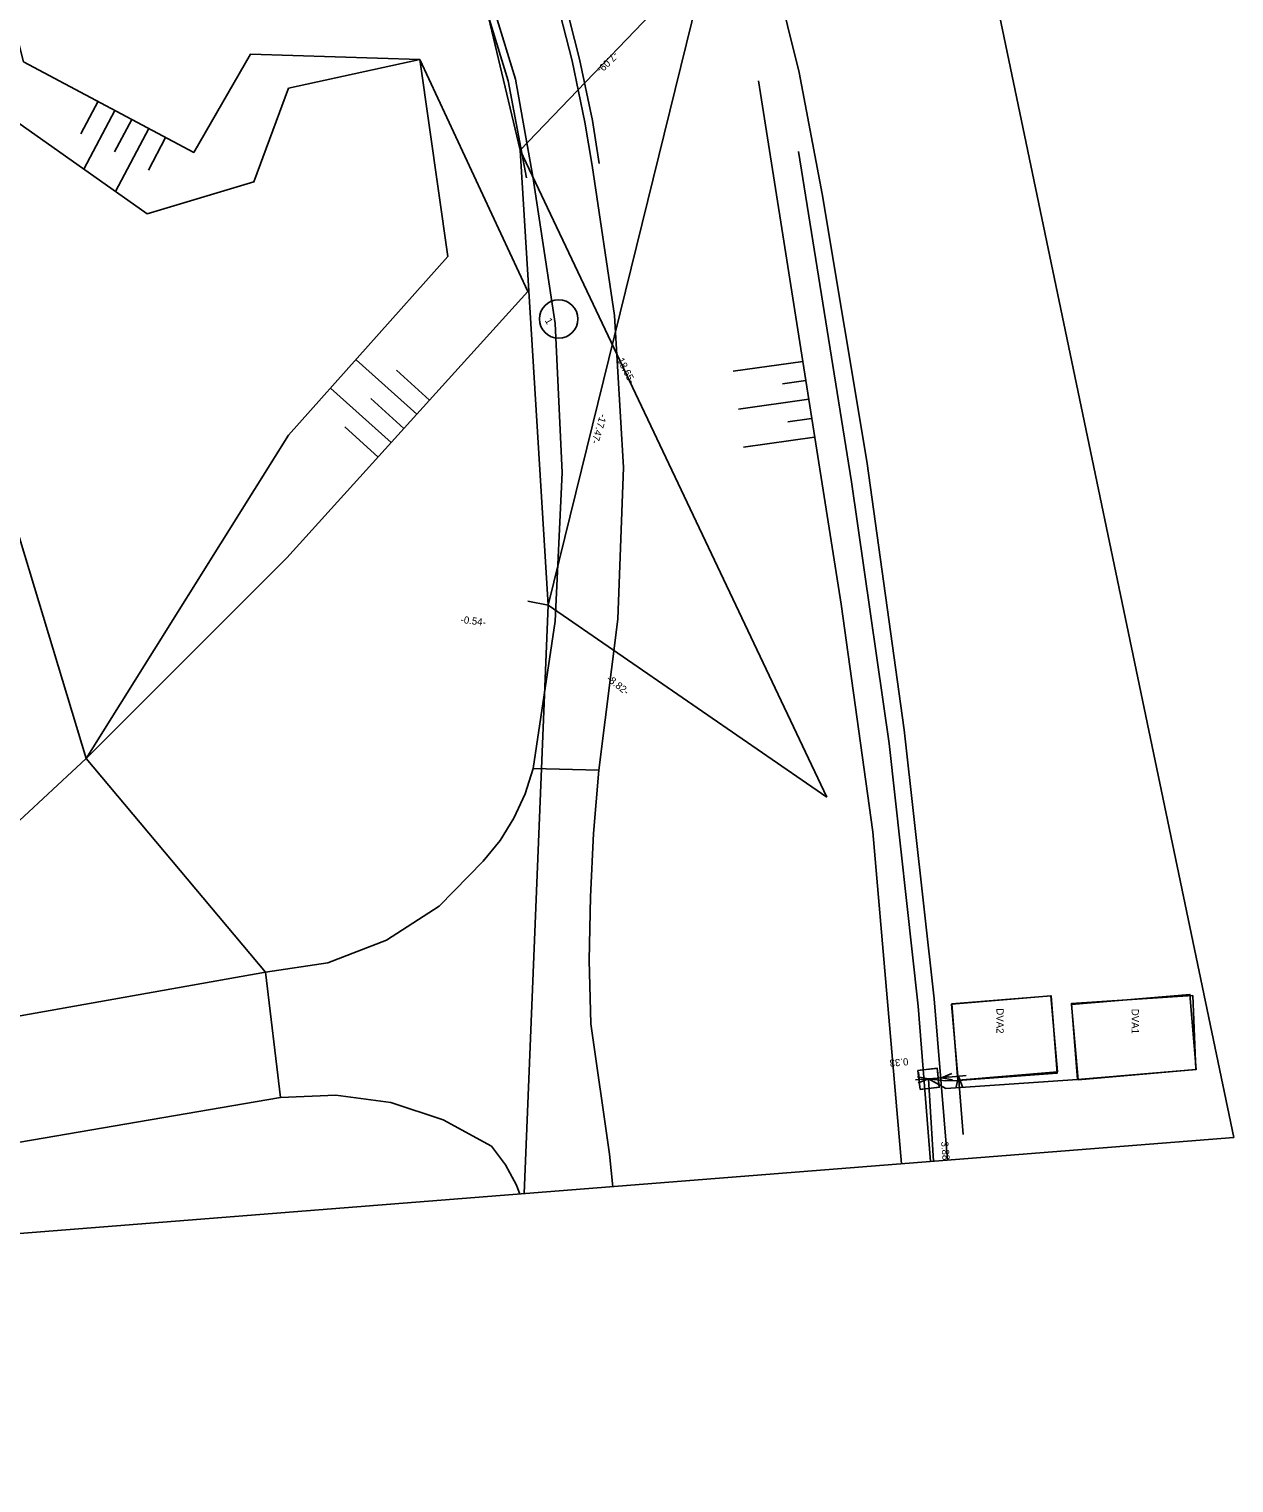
# Model space of a CAD drawing. Extents: x -597791 to -597535, y -1159670 to -1159547.
# Drawn here: x -597686.05 to -597654.67, y -1159669.54 to -1159631.67 of the extents above; entities that cross this region are included whole.
import ezdxf

# ---------------------------------------------------------------- set-up
doc = ezdxf.new("R2010")
doc.units = 0
for name, color, linetype in [('Kabely SSZ silové_Kabel SSZ_ kab', 7, 'Continuous'), ('Kabely SSZ silové_Oměrná SSZ', 7, 'Continuous'), ('Kabely SSZ silové_Text SSZ', 7, 'Continuous'), ('Koordinační kabel-Pom_KK Metalic', 7, 'Continuous'), ('Koordinační kabel-Pom_Oměrná KKM', 7, 'Continuous'), ('Koordinační kabel-Pom_Text KKM', 7, 'Continuous'), ('Koordinační kabel-Pom_Šachty KKM', 7, 'Continuous'), ('MAPA', 7, 'Continuous'), ('Ostatní', 7, 'Continuous'), ('Žádosti', 7, 'Continuous')]:
    doc.layers.add(name, color=color, linetype=linetype)

msp = doc.modelspace()

# ---------------------------------------------------------------- linework, layer by layer
at = {"layer": 'Kabely SSZ silové_Kabel SSZ_ kab'}
msp.add_line((-597662.49, -1159661.158), (-597662.62, -1159659.01), dxfattribs=at)
for points in [[(-597662.62, -1159659.01), (-597662.17, -1159659.26), (-597658.74, -1159659.03), (-597655.66, -1159658.77), (-597655.74, -1159656.84), (-597658.9, -1159657.05), (-597658.74, -1159659.03)], [(-597662.62, -1159659.01), (-597662.18, -1159659.06), (-597661.86, -1159659.05), (-597659.27, -1159658.86), (-597659.43, -1159656.85), (-597662.02, -1159657.06), (-597661.86, -1159659.05)]]:
    msp.add_lwpolyline(points, dxfattribs=at)
at = {"layer": 'Kabely SSZ silové_Oměrná SSZ'}
for points in [[(-597662.003, -1159659.035), (-597662.289, -1159658.98), (-597662.017, -1159658.875)], [(-597662.96, -1159659.04), (-597662.62, -1159659.01)], [(-597662.906, -1159658.955), (-597662.62, -1159659.01), (-597662.892, -1159659.114)], [(-597662.289, -1159658.98), (-597662.62, -1159659.01)], [(-597662.09, -1159658.962), (-597662.289, -1159658.98)], [(-597662.09, -1159658.964), (-597661.645, -1159658.927)], [(-597661.901, -1159659.229), (-597661.844, -1159658.944), (-597661.742, -1159659.216)], [(-597661.721, -1159660.456), (-597661.844, -1159658.944)]]:
    msp.add_lwpolyline(points, dxfattribs=at)
at = {"layer": 'Koordinační kabel-Pom_KK Metalic'}
msp.add_lwpolyline([(-597673.151, -1159662.001), (-597672.53, -1159646.67), (-597673.26, -1159634.82), (-597674.43, -1159629.89), (-597674.64, -1159626.96), (-597676.13, -1159624.16), (-597682.12, -1159607.29), (-597687.7, -1159594.16), (-597695.09, -1159580.13), (-597702.91, -1159567.07), (-597713.779, -1159550.637)], dxfattribs=at)
at = {"layer": 'Koordinační kabel-Pom_Oměrná KKM'}
for points in [[(-597668.35, -1159629.71), (-597673.26, -1159634.82)], [(-597672.53, -1159646.67), (-597668.35, -1159629.71)], [(-597673.26, -1159634.82), (-597665.27, -1159651.67)], [(-597672.53, -1159646.67), (-597673.06, -1159646.57)], [(-597672.53, -1159646.67), (-597665.27, -1159651.67)]]:
    msp.add_lwpolyline(points, dxfattribs=at)
at = {"layer": 'Koordinační kabel-Pom_Text KKM'}
msp.add_circle((-597672.255, -1159639.22), 0.5, dxfattribs=at)
at = {"layer": 'Koordinační kabel-Pom_Šachty KKM'}
for points in [[(-597662.888, -1159658.835), (-597662.849, -1159659.233)], [(-597662.445, -1159658.742), (-597662.843, -1159658.781)], [(-597662.352, -1159659.185), (-597662.391, -1159658.787)], [(-597662.795, -1159659.278), (-597662.397, -1159659.239)]]:
    msp.add_lwpolyline(points, dxfattribs=at)
at = {"layer": 'MAPA'}
for p, q in [((-597664.07, -1159652.58), (-597663.323, -1159661.224)), ((-597662.572, -1159661.165), (-597662.89, -1159657.12))]:
    msp.add_line(p, q, dxfattribs=at)
for points in [[(-597704.593, -1159549.561), (-597696.83, -1159561.36), (-597686.72, -1159577.97), (-597680.02, -1159590.93), (-597674.28, -1159604.46), (-597669.36, -1159619.22), (-597665.99, -1159632.8), (-597665.39, -1159635.96)], [(-597714.535, -1159550.725), (-597713.521, -1159552.063), (-597712.34, -1159553.62), (-597701.97, -1159569.58), (-597698.45, -1159581.43), (-597695.48, -1159594.37), (-597692.77, -1159605.67), (-597689.38, -1159619.96), (-597686.19, -1159632.52), (-597681.76, -1159634.88), (-597680.28, -1159632.32), (-597675.87, -1159632.46)], [(-597681.9, -1159602.47), (-597678.85, -1159610), (-597675.81, -1159618.47), (-597672.87, -1159627.9), (-597671.71, -1159632.45)], [(-597682.09, -1159602.55), (-597679.04, -1159610.07), (-597676, -1159618.53), (-597673.07, -1159627.96), (-597671.9, -1159632.5)], [(-597673.57, -1159633.02), (-597674.59, -1159629.69), (-597675.15, -1159627.78), (-597676.11, -1159624.21), (-597677.52, -1159620.27)], [(-597673.38, -1159632.97), (-597674.4, -1159629.63), (-597676.57, -1159622.22)], [(-597675.87, -1159632.46), (-597679.29, -1159633.21), (-597680.19, -1159635.65), (-597682.97, -1159636.48), (-597687.23, -1159633.48)], [(-597684.56, -1159650.67), (-597679.29, -1159642.25), (-597675.14, -1159637.59), (-597675.87, -1159632.46)], [(-597675.87, -1159632.46), (-597673.06, -1159638.5)], [(-597671.9, -1159632.5), (-597671.57, -1159634.09), (-597671.38, -1159635.22)], [(-597671.71, -1159632.45), (-597671.37, -1159634.05), (-597671.2, -1159635.17)], [(-597689.86, -1159633.14), (-597684.56, -1159650.67)], [(-597673.57, -1159633.02), (-597673.09, -1159635.54)], [(-597673.38, -1159632.97), (-597672.93, -1159635.51)], [(-597664.9, -1159646.65), (-597667.05, -1159633.02)], [(-597684.7, -1159634.4), (-597684.25, -1159633.55)], [(-597684.62, -1159635.32), (-597683.81, -1159633.79)], [(-597683.82, -1159634.87), (-597683.37, -1159634.02)], [(-597683.8, -1159635.9), (-597682.93, -1159634.26)], [(-597682.94, -1159635.34), (-597682.49, -1159634.49)], [(-597664.63, -1159643.46), (-597666.01, -1159634.86)], [(-597671.38, -1159635.22), (-597670.8, -1159639.13), (-597670.57, -1159643.09), (-597670.71, -1159647.04), (-597671.21, -1159650.97)], [(-597672.93, -1159635.51), (-597672.35, -1159639.34), (-597672.16, -1159643.22), (-597672.35, -1159647.09), (-597672.92, -1159650.93)], [(-597665.39, -1159635.96), (-597664.23, -1159642.92), (-597663.26, -1159649.92)], [(-597673.06, -1159638.5), (-597679.33, -1159645.44), (-597684.56, -1159650.67)], [(-597677.53, -1159640.28), (-597675.95, -1159641.7)], [(-597665.9, -1159640.33), (-597667.71, -1159640.58)], [(-597676.48, -1159640.55), (-597675.62, -1159641.33)], [(-597678.2, -1159641.02), (-597676.62, -1159642.44)], [(-597665.82, -1159640.82), (-597666.43, -1159640.91)], [(-597677.15, -1159641.29), (-597676.29, -1159642.07)], [(-597665.74, -1159641.31), (-597667.57, -1159641.57)], [(-597665.67, -1159641.81), (-597666.29, -1159641.9)], [(-597677.82, -1159642.03), (-597676.96, -1159642.82)], [(-597665.59, -1159642.3), (-597667.44, -1159642.56)], [(-597663.65, -1159650.28), (-597664.63, -1159643.46)], [(-597664.07, -1159652.58), (-597664.9, -1159646.65)], [(-597663.26, -1159649.92), (-597662.48, -1159656.93), (-597662.128, -1159661.13)], [(-597662.89, -1159657.12), (-597663.65, -1159650.28)], [(-597684.56, -1159650.67), (-597686.43, -1159652.4), (-597689.36, -1159654.01), (-597694.8, -1159655.94), (-597695.4, -1159656.12), (-597704.03, -1159658.79), (-597708.62, -1159659.55)], [(-597684.56, -1159650.67), (-597679.89, -1159656.23)], [(-597672.92, -1159650.93), (-597673.13, -1159651.59), (-597673.42, -1159652.22), (-597673.78, -1159652.8), (-597674.22, -1159653.34)], [(-597672.92, -1159650.93), (-597671.21, -1159650.97)], [(-597671.35, -1159652.62), (-597671.21, -1159650.97)], [(-597671.46, -1159655.92), (-597671.43, -1159654.27), (-597671.35, -1159652.62)], [(-597674.22, -1159653.34), (-597675.37, -1159654.51), (-597676.74, -1159655.4), (-597678.27, -1159655.99), (-597679.89, -1159656.23)], [(-597722.35, -1159659.75), (-597722.33, -1159660.94), (-597722.05, -1159661.47), (-597721.7, -1159661.74), (-597721.2, -1159661.86), (-597721.06, -1159661.85), (-597711.7, -1159661.44), (-597707.78, -1159661), (-597692.68, -1159658.51), (-597679.89, -1159656.23)], [(-597679.5, -1159659.5), (-597679.89, -1159656.23)], [(-597671.42, -1159657.58), (-597671.46, -1159655.92)], [(-597671.42, -1159657.58), (-597670.93, -1159660.97), (-597670.848, -1159661.819)], [(-597689.39, -1159661.19), (-597679.5, -1159659.5)], [(-597679.5, -1159659.5), (-597678.06, -1159659.44), (-597676.63, -1159659.63), (-597675.26, -1159660.08), (-597674, -1159660.76)], [(-597674, -1159660.76), (-597673.64, -1159661.25), (-597673.35, -1159661.78), (-597673.265, -1159662.01)]]:
    msp.add_lwpolyline(points, dxfattribs=at)
at = {"layer": 'Ostatní'}
for points in [[(-597661.852, -1159659.049), (-597659.266, -1159658.825), (-597659.436, -1159656.845), (-597662.022, -1159657.068)], [(-597658.73, -1159659.034), (-597655.65, -1159658.767), (-597655.818, -1159656.81), (-597658.898, -1159657.076)], [(-597662.898, -1159658.792), (-597662.838, -1159659.288), (-597662.342, -1159659.228), (-597662.402, -1159658.732)]]:
    msp.add_lwpolyline(points, close=True, dxfattribs=at)
at = {"layer": 'Žádosti'}
msp.add_lwpolyline([(-597654.67, -1159660.54), (-597678.483, -1159546.504), (-597791.46, -1159559.733), (-597772.145, -1159668.212), (-597768.441, -1159669.535)], close=True, dxfattribs=at)

# ---------------------------------------------------------------- texts
at = {"layer": 'Kabely SSZ silové_Oměrná SSZ'}
for s, rotation, p in [('0.33', 185.1073, (-597663.157, -1159658.468)), ('3.88', 274.6807, (-597662.296, -1159660.648))]:
    msp.add_text(s, height=0.1875, rotation=rotation, dxfattribs=at).set_placement(p)
at = {"layer": 'Kabely SSZ silové_Text SSZ'}
for s, p in [('DVA2', (-597660.853, -1159657.174)), ('DVA1', (-597657.333, -1159657.186))]:
    msp.add_text(s, height=0.1875, rotation=270, dxfattribs=at).set_placement(p)
at = {"layer": 'Koordinační kabel-Pom_Oměrná KKM'}
for s, rotation, p in [('-7.09-', 224.4041, (-597670.809, -1159632.245)), ('-18.65-', 297.2865, (-597670.777, -1159640.214)), ('-17.47-', 252.8006, (-597671.171, -1159641.679)), ('-0.54-', 352.912, (-597674.816, -1159647.135)), ('-8.82-', 321.7312, (-597671.026, -1159648.621))]:
    msp.add_text(s, height=0.1875, rotation=rotation, dxfattribs=at).set_placement(p)
at = {"layer": 'Koordinační kabel-Pom_Text KKM'}
msp.add_text('1', height=0.188, rotation=300.2, dxfattribs=at).set_placement((-597672.623, -1159639.258))

doc.saveas('drawing.dxf')
